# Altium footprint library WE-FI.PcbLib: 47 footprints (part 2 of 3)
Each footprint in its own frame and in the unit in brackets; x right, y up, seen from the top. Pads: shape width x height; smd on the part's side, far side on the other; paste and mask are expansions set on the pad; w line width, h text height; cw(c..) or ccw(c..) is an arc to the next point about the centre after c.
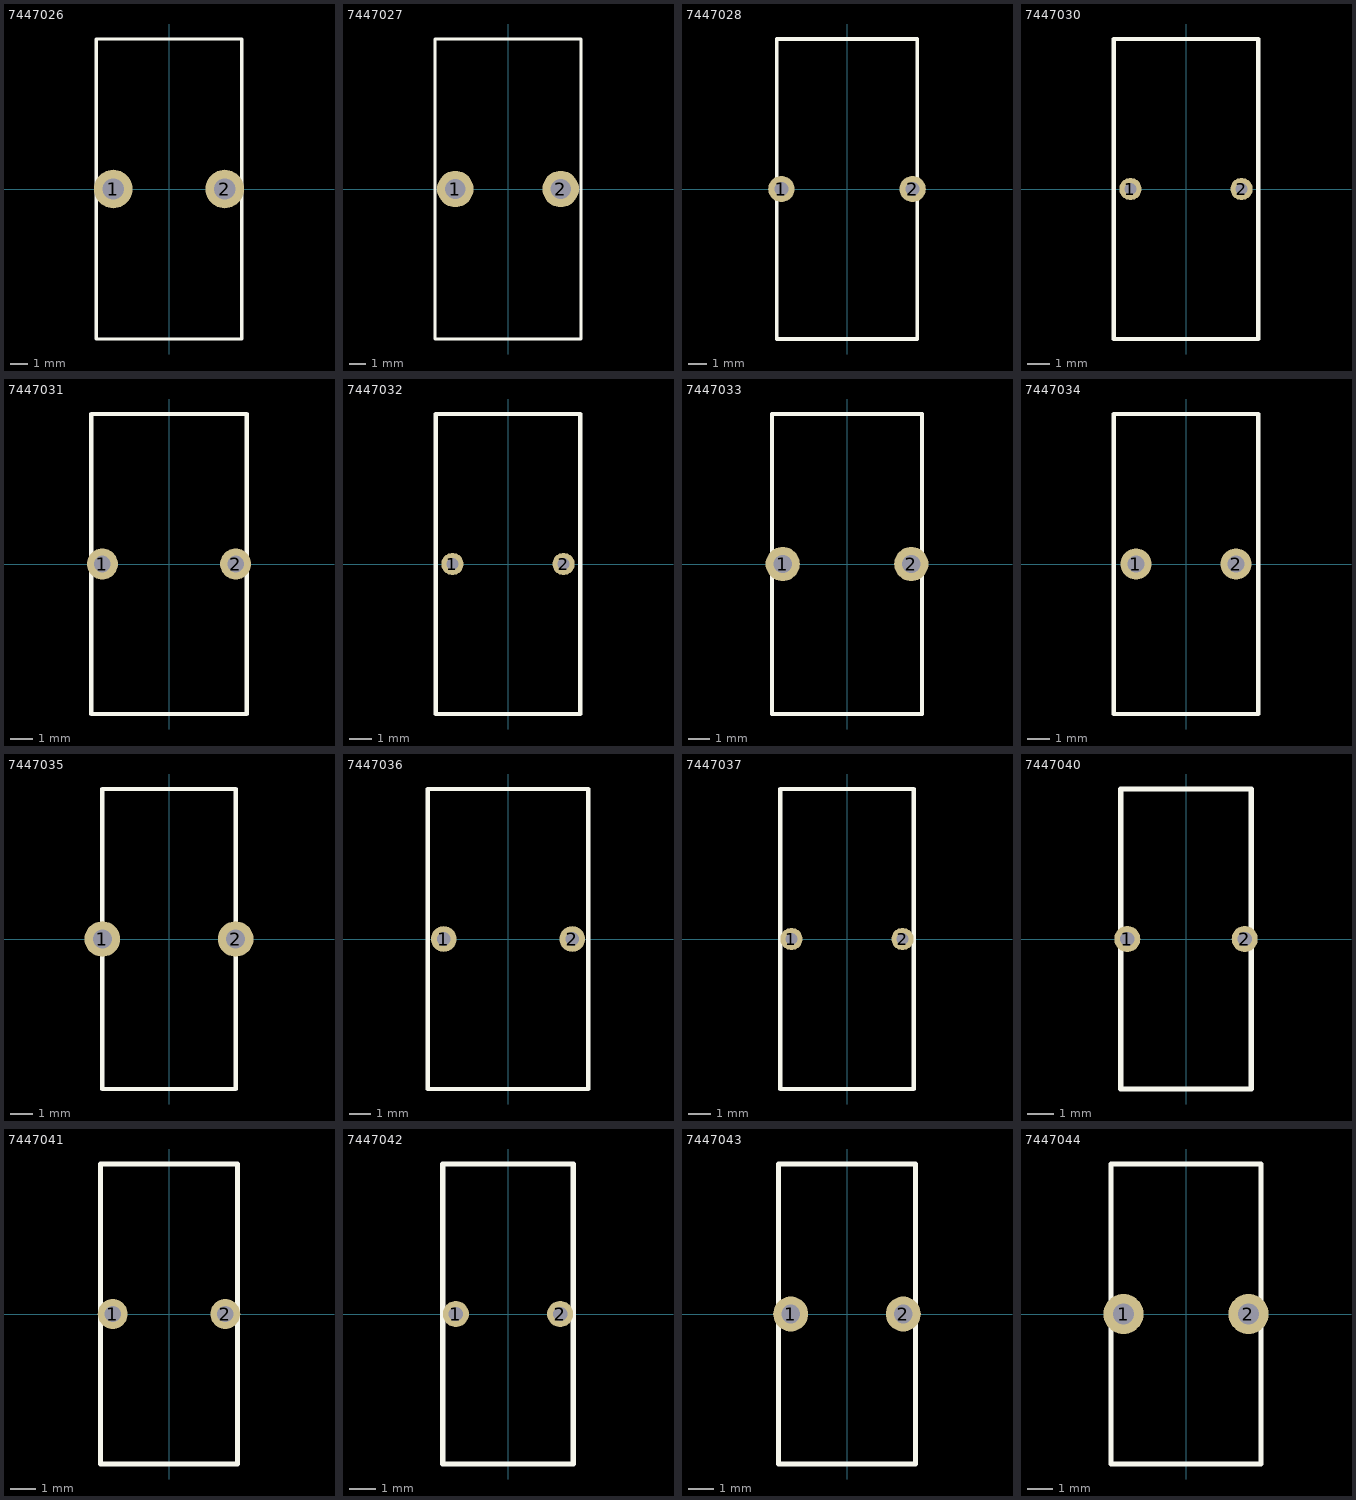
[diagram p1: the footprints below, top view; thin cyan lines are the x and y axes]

## 7447026 [mm] "Body 17.5x8.5mm, 2 leads"
height 17.5
pads (2):
  round 2.25 hole 1.25: 1(-3.25,0) 2(3.25,0)
Top Overlay:
  lines w0.2: -4.25,-8.75 -4.25,8.75 4.25,8.75 4.25,-8.75 -4.25,-8.75
3D body: height 19.18, standoff -6.75, extent -5.27,-9.748 5.27,9.747

## 7447027 [mm] "Body 18.5x9mm, 2 leads"
height 18.5
pads (2):
  round 2.25 hole 1.25: 1(-3.25,0) 2(3.25,0)
Top Overlay:
  lines w0.2: -4.5,-9.25 4.5,-9.25 4.5,9.25 -4.5,9.25 -4.5,-9.25
3D body: height 20.68, standoff -6.25, extent -5.52,-10.247 5.52,10.247

## 7447028 [mm] "Body 16x7.5mm, 2 leads"
height 16
pads (2):
  round 1.4 hole 0.75: 1(-3.5,0) 2(3.5,0)
Top Overlay:
  lines w0.2: -3.75,-8 -3.75,8 3.75,8 3.75,-8 -3.75,-8
3D body: height 17.55, standoff -19, extent -4.32,-8.566 4.32,8.566

## 7447030 [mm] "Body 13.5x6.5mm, 2 leads"
height 13.5
pads (2):
  round 1 hole 0.55: 1(-2.5,0) 2(2.5,0)
Top Overlay:
  lines w0.2: -3.25,-6.75 -3.25,6.75 3.25,6.75 3.25,-6.75 -3.25,-6.75
3D body: height 14.31, standoff -14, extent -3.32,-6.816 3.32,6.816

## 7447031 [mm] "Body 13.5x7mm, 2 leads"
height 13.5
pads (2):
  round 1.4 hole 0.75: 1(-3,0) 2(3,0)
Top Overlay:
  lines w0.2: -3.5,-6.75 -3.5,6.75 3.5,6.75 3.5,-6.75 -3.5,-6.75
3D body: height 14.74, standoff -14.25, extent -4.01,-7.254 4.01,7.253

## 7447032 [mm] "Body 13.5x6.5mm, 2 leads"
height 13.5
pads (2):
  round 1 hole 0.55: 1(-2.5,0) 2(2.5,0)
Top Overlay:
  lines w0.2: -3.25,-6.75 -3.25,6.75 3.25,6.75 3.25,-6.75 -3.25,-6.75
3D body: height 13.81, standoff -14.5, extent -3.07,-6.816 3.07,6.816

## 7447033 [mm] "Body 14x7mm, 2 leads"
height 14
pads (2):
  round 1.6 hole 0.85: 1(-3,0) 2(3,0)
Top Overlay:
  lines w0.2: -3.5,-7 -3.5,7 3.5,7 3.5,-7 -3.5,-7
3D body: height 15.6, standoff -14, extent -4.12,-7.613 4.12,7.614

## 7447034 [mm] "Body 13.5x6.5mm, 2 leads"
height 13.5
pads (2):
  round 1.4 hole 0.75: 1(-2.25,0) 2(2.25,0)
Top Overlay:
  lines w0.2: -3.25,-6.75 3.25,-6.75 3.25,6.75 -3.25,6.75 -3.25,-6.75
3D body: height 14.49, standoff -14, extent -3.76,-7.004 3.76,7.003

## 7447035 [mm] "Body 13.5x6mm, 2 leads"
height 13.5
pads (2):
  round 1.6 hole 0.85: 1(-3,0) 2(3,0)
Top Overlay:
  lines w0.2: -3,-6.75 -3,6.75 3,6.75 3,-6.75 -3,-6.75
3D body: height 14.8, standoff -14.25, extent -3.62,-7.352 3.62,7.351

## 7447036 [mm] "Body 14x7.5mm, 2 leads"
height 14
pads (2):
  round 1.2 hole 0.65: 1(-3,0) 2(3,0)
Top Overlay:
  lines w0.2: -3.75,-7 3.75,-7 3.75,7 -3.75,7 -3.75,-7
3D body: height 14.91, standoff -14.5, extent -4.17,-7.416 4.17,7.417

## 7447037 [mm] "Body 13.5x6mm, 2 leads"
height 13.5
pads (2):
  round 1 hole 0.55: 1(-2.5,0) 2(2.5,0)
Top Overlay:
  lines w0.2: -3,-6.75 -3,6.75 3,6.75 3,-6.75 -3,-6.75
3D body: height 14.56, standoff -14.25, extent -3.32,-7.066 3.32,7.067

## 7447040 [mm] "Body 11.5x5mm, 2 leads"
height 11.5
pads (2):
  round 1 hole 0.55: 1(-2.25,0) 2(2.25,0)
Top Overlay:
  lines w0.2: -2.5,-5.75 -2.5,5.75 2.5,5.75 2.5,-5.75 -2.5,-5.75
3D body: height 12.31, standoff -14.5, extent -2.821,-6.066 2.821,6.067

## 7447041 [mm] "Body 12x5.5mm, 2 leads"
height 12
pads (2):
  round 1.2 hole 0.65: 1(-2.25,0) 2(2.25,0)
Top Overlay:
  lines w0.2: -2.75,-6 2.75,-6 2.75,6 -2.75,6 -2.75,-6
3D body: height 12.89, standoff -14.5, extent -3.17,-6.411 3.17,6.412

## 7447042 [mm] "Body 11.5x5mm, 2 leads"
height 11.5
pads (2):
  round 1 hole 0.55: 1(-2,0) 2(2,0)
Top Overlay:
  lines w0.2: -2.5,-5.75 -2.5,5.75 2.5,5.75 2.5,-5.75 -2.5,-5.75
3D body: height 12.56, standoff -14.25, extent -2.821,-6.066 2.821,6.067

## 7447043 [mm] "Body 12x5.5mm, 2 leads"
height 12
pads (2):
  round 1.4 hole 0.75: 1(-2.25,0) 2(2.25,0)
Top Overlay:
  lines w0.2: -2.75,-6 2.75,-6 2.75,6 -2.75,6 -2.75,-6
3D body: height 13.49, standoff -14, extent -3.26,-6.504 3.26,6.505

## 7447044 [mm] "Body 12x6mm, 2 leads"
height 12
pads (2):
  round 1.6 hole 0.85: 1(-2.5,0) 2(2.5,0)
Top Overlay:
  lines w0.2: -3,-6 3,-6 3,6 -3,6 -3,-6
3D body: height 13.56, standoff -14, extent -3.62,-6.604 3.62,6.605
